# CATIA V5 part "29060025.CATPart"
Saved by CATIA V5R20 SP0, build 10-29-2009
Part number: 29060025
Definition: NONE
Nomenclature: 29060025
Source: Unknown
Description: 29060025
Bounding box of the stored display mesh (mm): x -12.5 to 44.548, y -44 to 78.548, z -34 to 34
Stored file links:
  C:\Users\Utente\Desktop\IO LAVORO\3D X SITO CF\X SITO\PLASTICA\RF1\29060025.CATPart
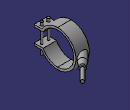
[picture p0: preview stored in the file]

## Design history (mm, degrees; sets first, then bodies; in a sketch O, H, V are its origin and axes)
Body1 "29060025" (main body)
  Solid1: solid without history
